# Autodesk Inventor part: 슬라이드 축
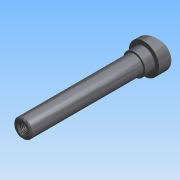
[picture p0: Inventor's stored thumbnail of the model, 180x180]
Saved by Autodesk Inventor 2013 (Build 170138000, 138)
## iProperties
Company: 한국ATC센터
Created: 2014-07
Part Number: 슬라이드 축
Document SubType Name: 모델링
Designer: KYOUNG IL JANG
Mass: 169.556 g
Surface Area: 67.5858 cm^2
Volume: 21.572 cm^3
Density: 7.86 g/cm^3
Material: 강철, 연강
변환 표준: STEP AP214IS
파일 이름: C:\Users\SeoGD\Desktop\?쒗뿕\異?stp
전처리기: Build: 253, Release: 2010 SP1 - Date: Wed 07/29/2009
전송 단위: 밀리미터
불확실성: 0.01
Author: KYOUNG IL JANG
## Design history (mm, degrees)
revolve "회전1" stored, may be unused: angle "d4" = 90 deg
sketch "스케치2"
  geometry: L1 (12.5, 0)-(12.5, -17) reference; L2 (-12.5, -17)-(12.5, -17) reference; L3 (-12.5, 0)-(-12.5, -17) reference; L4 (12.5, -5)-(-12.5, -11.699); L5 (-12.5, 0)-(12.5, 0) reference; 1 further point
  constraints: 2 end point, 2 point on line
  dimensions: "d5" = 75 deg angle of L1 L4; "d6" = 5 distance from line of L4.start L5
extrude "돌출1" cut sketch "스케치2" stored distance "d7" = 10; taper "d8" = 0 deg
chamfer "모따기1" distance "d9" = 1; stored, may be unused: second distance "d10" = 2, angle "d11" = 45 deg
fillet "모깎기1" dims "d12" = 0.5
hole "구멍1" diameter "d15" = 6.647; stored, may be unused: countersink angle "d19" = 90 deg, drill point angle "d21" = 118 deg; dims "d13" = 10, "d14" = 10, "d16" = 17, "d17" = 4, "d18" = 2, "d20" = 20
chamfer "모따기2" distance "d22" = 1; stored, may be unused: second distance "d23" = 2, angle "d24" = 45 deg
sketch "스케치3"
  geometry: C1 r 9 at (0, 0); 1 further point
  constraints: 1 centre point, 1 coincident
  dimensions: "d25" = 18 diameter of C1
extrude "돌출2" join sketch "스케치3" distance "d26" = 8; taper "d27" = 0 deg
node "솔리드1"
node "솔리드 본체"
node "곡면 본체"
sketch "스케치1"
  geometry: L1 (0, 100)-(7.5, 100); L2 (7.5, 100)-(7.5, 0); L3 (7.5, 0)-(12.5, 0); L4 (12.5, 0)-(12.5, -17); L5 (12.5, -17)-(0, -17); L6 (0, -17)-(0, 100); 1 further point
  constraints: 12 end point, 2 parallel, 2 point on line, 1 perpendicular, 1 vertical
  dimensions: "d0" = 100 distance from line of L1 point (0, 0); "d1" = 15 diameter of L2 L6; "d2" = 25 diameter of L4 L6; "d3" = 17 distance of L3.end L4.end
node "솔리드2"
